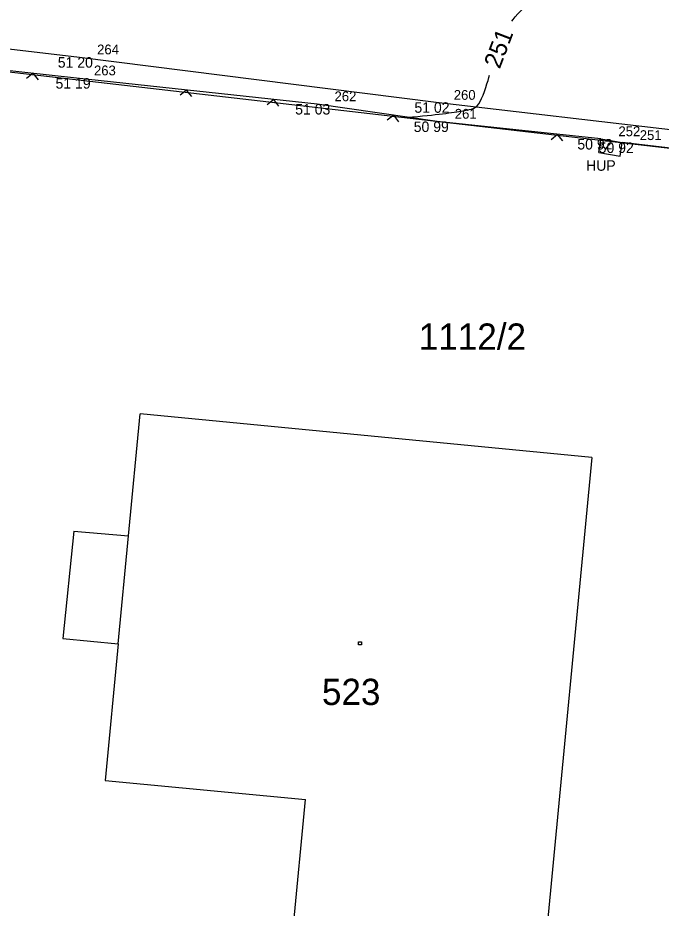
# Model space of a CAD drawing. Extents: x -704057 to -703795, y -1008732 to -1008584.
# Drawn here: x -703972.91 to -703954.51, y -1008681.82 to -1008656.35 of the extents above; entities that cross this region are included whole.
import ezdxf

# ---------------------------------------------------------------- set-up
doc = ezdxf.new("R2010")
doc.units = 0
for name, color, linetype in [('Z_body', 7, 'Continuous'), ('Z_body_cisla', 7, 'Continuous'), ('Z_body_vysky', 7, 'Continuous'), ('Z_katastr_cisla_pozemkove', 7, 'Continuous'), ('Z_katastr_cisla_stavebni', 7, 'Continuous'), ('Z_katastr_hranice', 7, 'Continuous'), ('Z_katastr_vnitrni_kresba', 7, 'Continuous'), ('Z_katastr_znacky', 7, 'Continuous'), ('Z_komunikace_zpevn_pl', 7, 'Continuous'), ('Z_oploceni', 7, 'Continuous'), ('Z_popis', 7, 'Continuous'), ('Z_site_pilire', 7, 'Continuous'), ('Z_vrstevnice_popis', 7, 'Continuous')]:
    doc.layers.add(name, color=color, linetype=linetype)

# ---------------------------------------------------------------- blocks, each defined once
blk = doc.blocks.new('POINT_DISPLAY')
blk.add_line((0, 0), (0, 0))
blk = doc.blocks.new('Z212')
for p, q in [((-0.17, 0.17), (0, 0)), ((0, 0), (0.17, 0.17))]:
    blk.add_line(p, q)
blk = doc.blocks.new('Z402')
for p, q in [((-0.03, 0.03), (0.05, 0.03)), ((-0.03, -0.05), (-0.03, 0.03)), ((0.05, 0.03), (0.05, -0.05)), ((0.05, -0.05), (-0.03, -0.05))]:
    blk.add_line(p, q)

msp = doc.modelspace()

# ---------------------------------------------------------------- linework, layer by layer
at = {"layer": 'Z_katastr_hranice'}
for p, q in [((-703977.9, -1008657.35), (-703947.65, -1008660.85)), ((-703969.74, -1008671.17), (-703969.41, -1008667.68)), ((-703956.49, -1008668.93), (-703969.41, -1008667.68)), ((-703956.49, -1008668.93), (-703957.98, -1008684.55)), ((-703971.31, -1008671.03), (-703971.62, -1008674.1)), ((-703971.31, -1008671.03), (-703969.74, -1008671.17)), ((-703971.62, -1008674.1), (-703970.04, -1008674.26)), ((-703970.04, -1008674.26), (-703970.41, -1008678.16)), ((-703970.41, -1008678.16), (-703964.68, -1008678.71)), ((-703965.17, -1008683.85), (-703964.68, -1008678.71))]:
    msp.add_line(p, q, dxfattribs=at)
at = {"layer": 'Z_katastr_vnitrni_kresba'}
msp.add_line((-703970.04, -1008674.26), (-703969.74, -1008671.17), dxfattribs=at)
at = {"layer": 'Z_komunikace_zpevn_pl'}
for p, q in [((-703980.15, -1008656.41), (-703971.14, -1008657.48)), ((-703971.14, -1008657.48), (-703960.94, -1008658.77)), ((-703960.94, -1008658.77), (-703950.78, -1008659.95))]:
    msp.add_line(p, q, dxfattribs=at)
at = {"layer": 'Z_oploceni'}
for p, q in [((-703971.23, -1008658.08), (-703977.9, -1008657.35)), ((-703964.35, -1008658.82), (-703971.23, -1008658.08)), ((-703960.91, -1008659.32), (-703964.35, -1008658.82)), ((-703956.23, -1008659.82), (-703960.91, -1008659.32)), ((-703950.82, -1008660.5), (-703955.62, -1008659.92))]:
    msp.add_line(p, q, dxfattribs=at)
at = {"layer": 'Z_site_pilire'}
for p, q in [((-703956.29, -1008660.21), (-703956.23, -1008659.82)), ((-703956.23, -1008659.82), (-703955.62, -1008659.92)), ((-703955.68, -1008660.31), (-703955.62, -1008659.92)), ((-703956.29, -1008660.21), (-703955.68, -1008660.31))]:
    msp.add_line(p, q, dxfattribs=at)
at = {"layer": 'Z_vrstevnice_popis'}
for points in [[(-703958.782, -1008656.452), (-703958.711, -1008656.345), (-703958.126, -1008655.591), (-703956.246, -1008655.482), (-703959.788, -1008654.246), (-703961.93, -1008651.293), (-703961.78, -1008651.126), (-703959.248, -1008651.187), (-703958.2, -1008651.305), (-703958.136, -1008651.315), (-703958.106, -1008651.318), (-703958.062, -1008651.325), (-703957.976, -1008651.334), (-703949.197, -1008652.35), (-703949.055, -1008652.366), (-703948.978, -1008652.372), (-703948.89, -1008652.368), (-703940.582, -1008653.06), (-703940.108, -1008653.095), (-703933.647, -1008653.758), (-703931.403, -1008653.997), (-703930.745, -1008653.985), (-703930.26, -1008654), (-703929.245, -1008652.825), (-703928.701, -1008652.453), (-703928.643, -1008652.6), (-703928.429, -1008652.279), (-703926.218, -1008652.574), (-703924.884, -1008652.504), (-703924.716, -1008652.484), (-703922.063, -1008653.995), (-703921.911, -1008654.006), (-703921.781, -1008654.024), (-703921.558, -1008654.048), (-703920.173, -1008654.162), (-703919.91, -1008654.188), (-703916.508, -1008654.023), (-703914.694, -1008654.331), (-703914.465, -1008654.432), (-703913.706, -1008654.968), (-703913.145, -1008655.151), (-703910.497, -1008655.228), (-703905.972, -1008655.203), (-703903.752, -1008655.504), (-703902.532, -1008655.695)], [(-703961.77, -1008659.195), (-703960.92, -1008659.137), (-703959.998, -1008658.98), (-703959.695, -1008658.941), (-703959.457, -1008658.142), (-703959.413, -1008657.996)]]:
    msp.add_open_spline(points, degree=3, dxfattribs=at)

# ---------------------------------------------------------------- block references
at = {"layer": 'Z_body'}
for p in [(-703971.14, -1008657.48), (-703971.23, -1008658.08), (-703964.35, -1008658.82), (-703960.94, -1008658.77), (-703960.91, -1008659.32), (-703956.23, -1008659.82), (-703955.62, -1008659.92)]:
    msp.add_blockref('POINT_DISPLAY', p, dxfattribs=at)
at = {"layer": 'Z_katastr_znacky'}
msp.add_blockref('Z402', (-703963.13, -1008674.23), dxfattribs=at)
at = {"layer": 'Z_oploceni'}
for p, rotation in [((-703972.47, -1008657.94), 173.8), ((-703968.08, -1008658.42), 173.9), ((-703965.59, -1008658.69), 173.9), ((-703962.15, -1008659.14), 171.7), ((-703957.47, -1008659.69), 173.9)]:
    msp.add_blockref('Z212', p, dxfattribs=dict(at, rotation=rotation))

# ---------------------------------------------------------------- texts
at = {"layer": 'Z_body_cisla'}
for s, p in [('264', (-703970.64, -1008657.4)), ('263', (-703970.73, -1008658)), ('262', (-703963.85, -1008658.74)), ('260', (-703960.44, -1008658.7)), ('261', (-703960.41, -1008659.24)), ('252', (-703955.73, -1008659.74)), ('251', (-703955.12, -1008659.85))]:
    msp.add_text(s, height=0.28, dxfattribs=at).set_placement(p)
at = {"layer": 'Z_body_vysky'}
for s, p in [('51 20', (-703971.765, -1008657.78)), ('51 19', (-703971.83, -1008658.38)), ('51 03', (-703964.975, -1008659.12)), ('51 02', (-703961.565, -1008659.07)), ('50 99', (-703961.585, -1008659.62)), ('50 92', (-703956.905, -1008660.12)), ('50 92', (-703956.295, -1008660.22))]:
    msp.add_text(s, height=0.3, dxfattribs=at).set_placement(p)
at = {"layer": 'Z_katastr_cisla_pozemkove'}
msp.add_text('1112/2', height=0.75, dxfattribs=at).set_placement((-703961.44, -1008665.845))
at = {"layer": 'Z_katastr_cisla_stavebni'}
msp.add_text('523', height=0.75, dxfattribs=at).set_placement((-703964.21, -1008676.005))
at = {"layer": 'Z_popis'}
msp.add_text('HUP', height=0.3, dxfattribs=at).set_placement((-703956.655, -1008660.729))
at = {"layer": 'Z_vrstevnice_popis'}
msp.add_text('251', height=0.5, rotation=69.098, dxfattribs=at).set_placement((-703959.126, -1008657.838))

doc.saveas('drawing.dxf')
